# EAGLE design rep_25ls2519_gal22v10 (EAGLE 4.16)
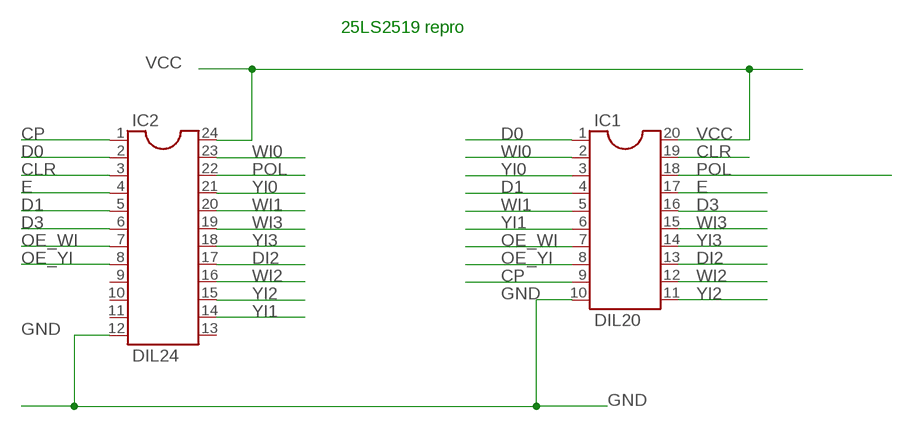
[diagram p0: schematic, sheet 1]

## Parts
IC1  DIL20  [DIL20]
IC2  DIL24  [DIL24-3]

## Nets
CLR: IC1.19 IC2.3
CP: IC1.9 IC2.1
D0: IC1.1 IC2.2
D1: IC1.4 IC2.5
D3: IC1.16 IC2.6
DI2: IC1.13 IC2.17
E: IC1.17 IC2.4
GND: IC1.10 IC2.12
OE_WI: IC1.7 IC2.7
OE_YI: IC1.8 IC2.8
POL: IC1.18 IC2.22
VCC: IC1.20 IC2.24
WI0: IC1.2 IC2.23
WI1: IC1.5 IC2.20
WI2: IC1.12 IC2.16
WI3: IC1.15 IC2.19
YI0: IC1.3 IC2.21
YI1: IC1.6 IC2.14
YI2: IC1.11 IC2.15
YI3: IC1.14 IC2.18
Unconnected: IC2.9 IC2.10 IC2.11 IC2.13

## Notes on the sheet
- 25LS2519 repro

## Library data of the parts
IC1 = DIL:DIL20
IC2 = dil@2:DIL24

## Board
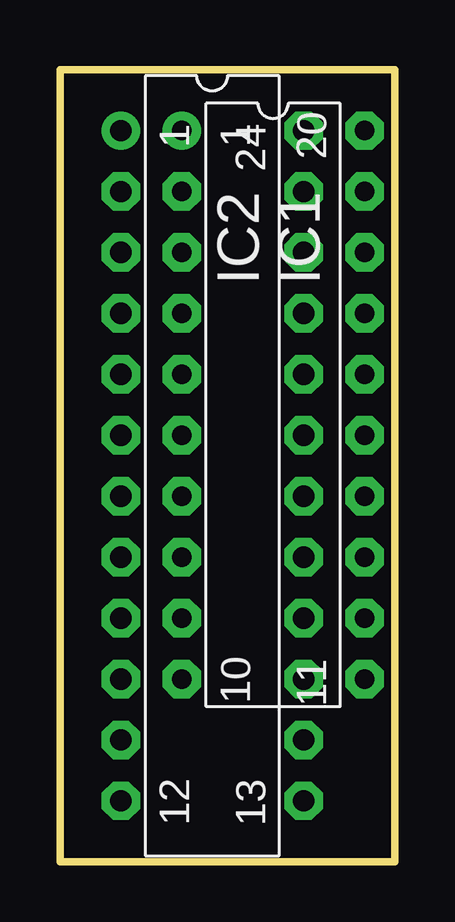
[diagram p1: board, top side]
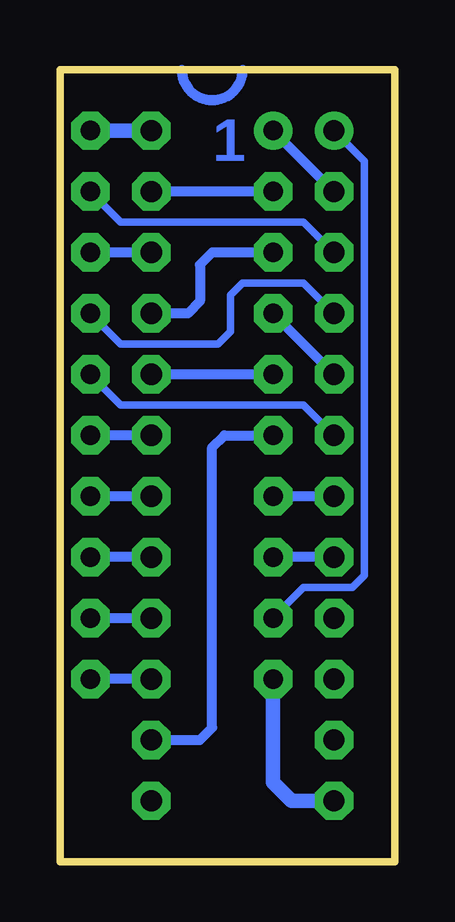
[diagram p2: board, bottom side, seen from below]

Size 13.97 x 33.02 mm. Coordinates in mm from the lower left corner, seen from the top.
Outline: 0,33.02 13.97,33.02 13.97,0 0,0 0,33.02
Copper layers (1*16): Top 0.035mm / dielectric 1.5mm / Bottom 0.035mm
Design rules "default": minimum track width 10mil, minimum drill 24mil, track to track 8mil, track to pad 8mil, pad to pad 8mil, via to via 8mil, smd to smd 8mil, copper to edge 40mil, drill to drill 8mil, minimum pad ring 10mil, minimum via ring 8mil, stop-mask expansion 4mil, vias tented up to drill 0mil, thermal gap 10mil

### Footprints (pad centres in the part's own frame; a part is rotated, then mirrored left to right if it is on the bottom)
DIL20 = drill 0.813 pad 1.6 round: 1 -11.43,-3.81 | drill 0.813 pad 1.6 octagon: 2 -8.89,-3.81; 3 -6.35,-3.81; 4 -3.81,-3.81; 5 -1.27,-3.81; 6 1.27,-3.81; 7 3.81,-3.81; 8 6.35,-3.81; 9 8.89,-3.81; 10 11.43,-3.81; 11 11.43,3.81; 12 8.89,3.81; 13 6.35,3.81; 14 3.81,3.81; 15 1.27,3.81; 16 -1.27,3.81; 17 -3.81,3.81; 18 -6.35,3.81; 19 -8.89,3.81; 20 -11.43,3.81
DIL24-3 = drill 0.889 pad 1.6 round: 1 -13.97,-3.81 | drill 0.889 pad 1.6 octagon: 2 -11.43,-3.81; 3 -8.89,-3.81; 4 -6.35,-3.81; 5 -3.81,-3.81; 6 -1.27,-3.81; 7 1.27,-3.81; 8 3.81,-3.81; 9 6.35,-3.81; 10 8.89,-3.81; 11 11.43,-3.81; 12 13.97,-3.81; 13 13.97,3.81; 14 11.43,3.81; 15 8.89,3.81; 16 6.35,3.81; 17 3.81,3.81; 18 1.27,3.81; 19 -1.27,3.81; 20 -3.81,3.81; 21 -6.35,3.81; 22 -8.89,3.81; 23 -11.43,3.81; 24 -13.97,3.81

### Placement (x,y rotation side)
IC1  8.89,19.05 270 top
IC2  6.35,16.51 270 top

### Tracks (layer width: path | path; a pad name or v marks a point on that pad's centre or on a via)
CLR
  Bottom 0.305: IC2.3 3.81,26.67 11.43,26.67 IC1.19
CP
  Bottom 0.305: IC2.1 1.27,29.21 1.27,11.94 1.78,11.43 3.81,11.43 IC1.9
D0
  Bottom 0.406: IC2.2 IC1.1
D1
  Bottom 0.406: IC2.5 IC1.4
D3
  Bottom 0.305: IC2.6 3.81,19.05 11.43,19.05 IC1.16
DI2
  Bottom 0.406: IC2.17 IC1.13
E
  Bottom 0.305: IC2.4 3.81,24.13 6.35,24.13 6.86,23.62 6.86,22.1 7.37,21.59 11.43,21.59 IC1.17
GND
  Bottom 0.61: IC2.12 4.32,2.54 5.08,3.3 IC1.10
N$1
  Bottom 0.406: 8.89,33.02 arc-180 6.35,33.02
OE_WI
  Bottom 0.406: IC1.7 IC2.7
OE_YI
  Bottom 0.406: IC2.8 IC1.8
POL
  Bottom 0.406: IC2.22 IC1.18
VCC
  Bottom 0.61: IC2.24 IC1.20
WI0
  Bottom 0.406: IC1.2 IC2.23
WI1
  Bottom 0.406: IC1.5 IC2.20
WI2
  Bottom 0.406: IC1.12 IC2.16
WI3
  Bottom 0.406: IC2.19 IC1.15
YI0
  Bottom 0.406: IC1.3 7.62,25.4 8.13,24.89 8.13,23.37 8.64,22.86 IC2.21
YI1
  Bottom 0.406: IC2.14 8.13,5.08 7.62,5.59 7.62,17.27 7.11,17.78 IC1.6
YI2
  Bottom 0.406: IC2.15 IC1.11
YI3
  Bottom 0.406: IC1.14 IC2.18

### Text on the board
Bottom: 1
